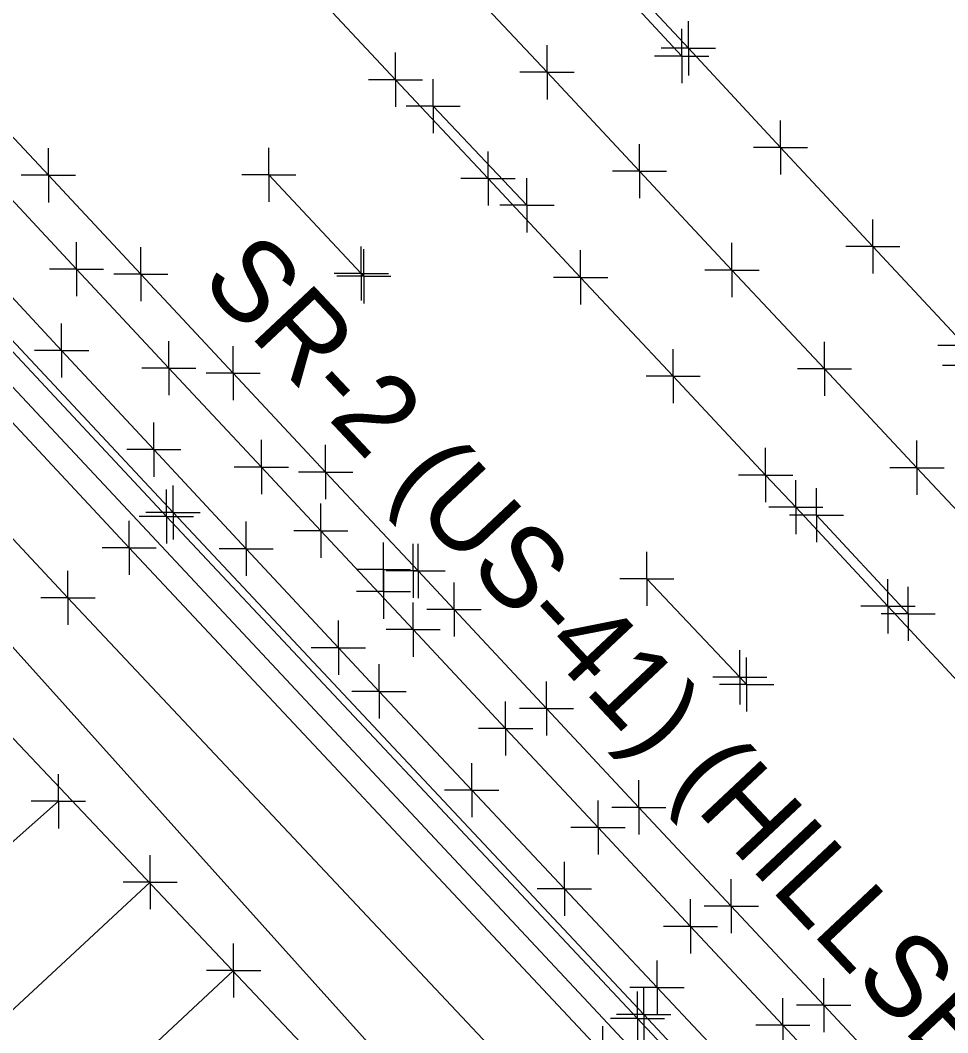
# Model space of a CAD drawing. Extents: x 0 to 1944463, y 0 to 420651.
# Drawn here: x 1943576.1 to 1943644.6, y 416958.1 to 417032.9 of the extents above; entities that cross this region are included whole.
import ezdxf

# ---------------------------------------------------------------- set-up
doc = ezdxf.new("R2010")
doc.units = 0
for name, color, linetype in [('SUR - DTM - Breaklines', 7, 'Continuous'), ('SUR - DTM - Breaklines - Points - Locators', 7, 'Continuous'), ('SUR - PROPERTY - Property Lines', 7, 'Continuous'), ('SUR - TR-CTRL - Pavement Marking', 7, 'Continuous'), ('SUR - TR-CTRL - Pavement Marking - Points - Locators', 7, 'Continuous'), ('SUR - TRAN - Features', 7, 'Continuous'), ('SUR - TRAN - Features - Points - Locators', 7, 'Continuous'), ('SUR - TRAN - Roads', 7, 'Continuous'), ('SUR - TRAN - Roads Text', 7, 'Continuous'), ('SUR - UTL - Fiber Optic Cable (Underground)', 7, 'Continuous'), ('SUR - UTL - Overhead Wire Crossings', 7, 'Continuous')]:
    doc.layers.add(name, color=color, linetype=linetype)

msp = doc.modelspace()

# ---------------------------------------------------------------- linework, layer by layer
at = {"layer": 'SUR - DTM - Breaklines'}
for points in [[(1943690.037, 416884.41), (1943687.662, 416887.901), (1943684.141, 416892.114), (1943657.009, 416921.299), (1943621.67, 416959.115), (1943586.87, 416996.211), (1943552.435, 417033.099), (1943548.063, 417037.789), (1943547.477, 417038.396), (1943544.67, 417041.299), (1943541.061, 417045.18), (1943540.584, 417045.813), (1943504.988, 417083.827), (1943481.846, 417108.505), (1943446.671, 417146.1), (1943414.771, 417178.279)], [(1943539.852, 417109.374), (1943546.682, 417102.07), (1943553.513, 417094.766), (1943560.343, 417087.462), (1943567.173, 417080.158), (1943574.003, 417072.854), (1943580.834, 417065.551), (1943587.664, 417058.247), (1943594.494, 417050.943), (1943601.325, 417043.639), (1943608.155, 417036.335), (1943614.985, 417029.031), (1943621.815, 417021.727), (1943628.646, 417014.423), (1943635.476, 417007.119), (1943642.306, 416999.815), (1943649.136, 416992.511), (1943655.967, 416985.207), (1943662.797, 416977.903), (1943669.627, 416970.599), (1943676.457, 416963.295), (1943683.288, 416955.991)]]:
    msp.add_lwpolyline(points, dxfattribs=at)
at = {"layer": 'SUR - DTM - Breaklines - Points - Locators'}
for p, q in [((1943614.985, 417029.031), (1943614.985, 417031.031)), ((1943614.985, 417029.031), (1943612.985, 417029.031)), ((1943614.985, 417029.031), (1943616.985, 417029.031)), ((1943614.985, 417029.031), (1943614.985, 417027.031)), ((1943621.815, 417021.727), (1943621.815, 417023.727)), ((1943621.815, 417021.727), (1943619.815, 417021.727)), ((1943621.815, 417021.727), (1943623.815, 417021.727)), ((1943621.815, 417021.727), (1943621.815, 417019.727)), ((1943628.646, 417014.423), (1943628.646, 417016.423)), ((1943628.646, 417014.423), (1943626.646, 417014.423)), ((1943628.646, 417014.423), (1943630.646, 417014.423)), ((1943628.646, 417014.423), (1943628.646, 417012.423)), ((1943635.476, 417007.119), (1943635.476, 417009.119)), ((1943635.476, 417007.119), (1943633.476, 417007.119)), ((1943635.476, 417007.119), (1943637.476, 417007.119)), ((1943635.476, 417007.119), (1943635.476, 417005.119)), ((1943642.306, 416999.815), (1943642.306, 417001.815)), ((1943642.306, 416999.815), (1943640.306, 416999.815)), ((1943642.306, 416999.815), (1943644.306, 416999.815)), ((1943642.306, 416999.815), (1943642.306, 416997.815)), ((1943586.87, 416996.211), (1943586.87, 416998.211)), ((1943586.87, 416996.211), (1943584.87, 416996.211)), ((1943586.87, 416996.211), (1943588.87, 416996.211)), ((1943586.87, 416996.211), (1943586.87, 416994.211)), ((1943621.67, 416959.115), (1943621.67, 416961.115)), ((1943621.67, 416959.115), (1943619.67, 416959.115)), ((1943621.67, 416959.115), (1943623.67, 416959.115)), ((1943621.67, 416959.115), (1943621.67, 416957.115))]:
    msp.add_line(p, q, dxfattribs=at)
at = {"layer": 'SUR - PROPERTY - Property Lines'}
for p, q in [((1943579.134, 417008.475), (1943579.134, 417010.475)), ((1943579.134, 417008.475), (1943577.134, 417008.475)), ((1943579.134, 417008.475), (1943581.134, 417008.475)), ((1943579.134, 417008.475), (1943579.134, 417006.475)), ((1943585.948, 417001.155), (1943585.948, 417003.155)), ((1943585.948, 417001.155), (1943583.948, 417001.155)), ((1943585.948, 417001.155), (1943587.948, 417001.155)), ((1943585.948, 417001.155), (1943585.948, 416999.155)), ((1943592.762, 416993.836), (1943592.762, 416995.836)), ((1943592.762, 416993.836), (1943590.762, 416993.836)), ((1943592.762, 416993.836), (1943594.762, 416993.836)), ((1943592.762, 416993.836), (1943592.762, 416991.836)), ((1943599.576, 416986.517), (1943599.576, 416988.517)), ((1943599.576, 416986.517), (1943597.576, 416986.517)), ((1943599.576, 416986.517), (1943601.576, 416986.517)), ((1943599.576, 416986.517), (1943599.576, 416984.517)), ((1943602.577, 416983.292), (1943602.577, 416985.292)), ((1943602.577, 416983.292), (1943600.577, 416983.292)), ((1943602.577, 416983.292), (1943604.577, 416983.292)), ((1943602.577, 416983.292), (1943602.577, 416981.292)), ((1943609.421, 416976.001), (1943609.421, 416978.001)), ((1943609.421, 416976.001), (1943607.421, 416976.001)), ((1943609.421, 416976.001), (1943611.421, 416976.001)), ((1943609.421, 416976.001), (1943609.421, 416974.001)), ((1943616.265, 416968.71), (1943616.265, 416970.71)), ((1943616.265, 416968.71), (1943614.265, 416968.71)), ((1943616.265, 416968.71), (1943618.265, 416968.71)), ((1943616.265, 416968.71), (1943616.265, 416966.71)), ((1943623.109, 416961.419), (1943623.109, 416963.419)), ((1943623.109, 416961.419), (1943621.109, 416961.419)), ((1943623.109, 416961.419), (1943625.109, 416961.419)), ((1943623.109, 416961.419), (1943623.109, 416959.419))]:
    msp.add_line(p, q, dxfattribs=at)
at = {"layer": 'SUR - TR-CTRL - Pavement Marking'}
for points in [[(1943550.497, 417111.213), (1943557.317, 417103.9), (1943564.137, 417096.586), (1943570.957, 417089.273), (1943577.778, 417081.96), (1943584.598, 417074.646), (1943591.418, 417067.333), (1943598.176, 417060.086), (1943604.988, 417052.765), (1943611.799, 417045.443), (1943618.611, 417038.122), (1943625.423, 417030.801), (1943632.234, 417023.479), (1943639.046, 417016.158), (1943645.857, 417008.837), (1943652.669, 417001.515), (1943655.246, 416998.746), (1943662.07, 416991.437), (1943668.895, 416984.128), (1943675.72, 416976.819), (1943682.545, 416969.51), (1943689.369, 416962.201), (1943696.194, 416954.892)], [(1943499.195, 417106.006), (1943506.035, 417098.711), (1943512.875, 417091.417), (1943519.716, 417084.122), (1943520.96, 417082.795), (1943527.773, 417075.474), (1943534.585, 417068.154), (1943541.397, 417060.833), (1943548.21, 417053.513), (1943555.022, 417046.192), (1943557.674, 417043.342), (1943564.5, 417036.034), (1943571.327, 417028.727), (1943578.153, 417021.419), (1943584.979, 417014.111), (1943591.805, 417006.803), (1943598.631, 416999.495), (1943605.457, 416992.187), (1943608.116, 416989.341), (1943614.942, 416982.033), (1943621.768, 416974.725), (1943628.595, 416967.418), (1943635.421, 416960.11), (1943642.247, 416952.802)], [(1943573.276, 417061.102), (1943576.462, 417057.683), (1943583.296, 417050.382), (1943590.13, 417043.082), (1943596.963, 417035.781), (1943603.797, 417028.481), (1943610.631, 417021.18), (1943617.465, 417013.879), (1943624.299, 417006.579), (1943631.133, 416999.278), (1943633.357, 416996.902), (1943640.169, 416989.581), (1943646.98, 416982.26), (1943653.792, 416974.938), (1943660.604, 416967.617), (1943667.416, 416960.296), (1943674.227, 416952.975)], [(1943618.188, 417037.513), (1943624.93, 417030.233)], [(1943606.569, 417026.524), (1943613.502, 417019.206)], [(1943594.432, 417021.46), (1943601.266, 417014.16), (1943601.456, 417013.957)], [(1943634.884, 416996.304), (1943641.665, 416989.024)], [(1943602.909, 416990.66), (1943602.909, 416992.302), (1943605.103, 416992.2)], [(1943622.363, 416991.612), (1943629.221, 416984.334), (1943629.729, 416983.795)], [(1943578.894, 416975.171), (1943564.666, 416962.579)], [(1943571.121, 416955.695), (1943585.673, 416969.203)], [(1943591.838, 416962.671), (1943577.197, 416949.004)]]:
    msp.add_lwpolyline(points, dxfattribs=at)
at = {"layer": 'SUR - TR-CTRL - Pavement Marking - Points - Locators'}
for p, q in [((1943625.423, 417030.801), (1943625.423, 417032.801)), ((1943624.93, 417030.233), (1943624.93, 417032.233)), ((1943625.423, 417030.801), (1943623.423, 417030.801)), ((1943625.423, 417030.801), (1943627.423, 417030.801)), ((1943625.423, 417030.801), (1943625.423, 417028.801)), ((1943603.797, 417028.481), (1943603.797, 417030.481)), ((1943624.93, 417030.233), (1943622.93, 417030.233)), ((1943624.93, 417030.233), (1943626.93, 417030.233)), ((1943624.93, 417030.233), (1943624.93, 417028.233)), ((1943603.797, 417028.481), (1943601.797, 417028.481)), ((1943603.797, 417028.481), (1943605.797, 417028.481)), ((1943603.797, 417028.481), (1943603.797, 417026.481)), ((1943606.569, 417026.524), (1943606.569, 417028.524)), ((1943606.569, 417026.524), (1943604.569, 417026.524)), ((1943606.569, 417026.524), (1943608.569, 417026.524)), ((1943606.569, 417026.524), (1943606.569, 417024.524)), ((1943632.234, 417023.479), (1943632.234, 417025.479)), ((1943578.153, 417021.419), (1943578.153, 417023.419)), ((1943594.432, 417021.46), (1943594.432, 417023.46)), ((1943632.234, 417023.479), (1943630.234, 417023.479)), ((1943632.234, 417023.479), (1943634.234, 417023.479)), ((1943632.234, 417023.479), (1943632.234, 417021.479)), ((1943610.631, 417021.18), (1943610.631, 417023.18)), ((1943578.153, 417021.419), (1943576.153, 417021.419)), ((1943578.153, 417021.419), (1943580.153, 417021.419)), ((1943578.153, 417021.419), (1943578.153, 417019.419)), ((1943594.432, 417021.46), (1943592.432, 417021.46)), ((1943594.432, 417021.46), (1943596.432, 417021.46)), ((1943594.432, 417021.46), (1943594.432, 417019.46)), ((1943610.631, 417021.18), (1943608.631, 417021.18)), ((1943610.631, 417021.18), (1943612.631, 417021.18)), ((1943610.631, 417021.18), (1943610.631, 417019.18)), ((1943613.502, 417019.206), (1943613.502, 417021.206)), ((1943613.502, 417019.206), (1943611.502, 417019.206)), ((1943613.502, 417019.206), (1943615.502, 417019.206)), ((1943613.502, 417019.206), (1943613.502, 417017.206)), ((1943639.046, 417016.158), (1943639.046, 417018.158)), ((1943584.979, 417014.111), (1943584.979, 417016.111)), ((1943601.266, 417014.16), (1943601.266, 417016.16)), ((1943601.456, 417013.957), (1943601.456, 417015.957)), ((1943617.465, 417013.879), (1943617.465, 417015.879)), ((1943639.046, 417016.158), (1943637.046, 417016.158)), ((1943639.046, 417016.158), (1943641.046, 417016.158)), ((1943639.046, 417016.158), (1943639.046, 417014.158)), ((1943584.979, 417014.111), (1943582.979, 417014.111)), ((1943584.979, 417014.111), (1943586.979, 417014.111)), ((1943584.979, 417014.111), (1943584.979, 417012.111)), ((1943601.266, 417014.16), (1943599.266, 417014.16)), ((1943601.456, 417013.957), (1943599.456, 417013.957)), ((1943601.266, 417014.16), (1943603.266, 417014.16)), ((1943601.266, 417014.16), (1943601.266, 417012.16)), ((1943601.456, 417013.957), (1943603.456, 417013.957)), ((1943601.456, 417013.957), (1943601.456, 417011.957)), ((1943617.465, 417013.879), (1943615.465, 417013.879)), ((1943617.465, 417013.879), (1943619.465, 417013.879)), ((1943617.465, 417013.879), (1943617.465, 417011.879)), ((1943591.805, 417006.803), (1943591.805, 417008.803)), ((1943624.299, 417006.579), (1943624.299, 417008.579)), ((1943645.857, 417008.837), (1943643.857, 417008.837)), ((1943646.187, 417007.368), (1943644.187, 417007.368)), ((1943591.805, 417006.803), (1943589.805, 417006.803)), ((1943591.805, 417006.803), (1943593.805, 417006.803)), ((1943591.805, 417006.803), (1943591.805, 417004.803)), ((1943624.299, 417006.579), (1943622.299, 417006.579)), ((1943624.299, 417006.579), (1943626.299, 417006.579)), ((1943624.299, 417006.579), (1943624.299, 417004.579)), ((1943598.631, 416999.495), (1943598.631, 417001.495)), ((1943631.133, 416999.278), (1943631.133, 417001.278)), ((1943598.631, 416999.495), (1943596.631, 416999.495)), ((1943598.631, 416999.495), (1943600.631, 416999.495)), ((1943598.631, 416999.495), (1943598.631, 416997.495)), ((1943631.133, 416999.278), (1943629.133, 416999.278)), ((1943631.133, 416999.278), (1943633.133, 416999.278)), ((1943631.133, 416999.278), (1943631.133, 416997.278)), ((1943633.357, 416996.902), (1943633.357, 416998.902)), ((1943634.884, 416996.304), (1943634.884, 416998.304)), ((1943633.357, 416996.902), (1943631.357, 416996.902)), ((1943633.357, 416996.902), (1943635.357, 416996.902)), ((1943633.357, 416996.902), (1943633.357, 416994.902)), ((1943634.884, 416996.304), (1943632.884, 416996.304)), ((1943634.884, 416996.304), (1943636.884, 416996.304)), ((1943634.884, 416996.304), (1943634.884, 416994.304)), ((1943602.909, 416992.302), (1943602.909, 416994.302)), ((1943605.103, 416992.2), (1943605.103, 416994.2)), ((1943605.457, 416992.187), (1943605.457, 416994.187)), ((1943622.363, 416991.612), (1943622.363, 416993.612)), ((1943602.909, 416990.66), (1943602.909, 416992.66)), ((1943602.909, 416992.302), (1943600.909, 416992.302)), ((1943602.909, 416992.302), (1943604.909, 416992.302)), ((1943602.909, 416992.302), (1943602.909, 416990.302)), ((1943605.103, 416992.2), (1943603.103, 416992.2)), ((1943605.457, 416992.187), (1943603.457, 416992.187)), ((1943605.103, 416992.2), (1943607.103, 416992.2)), ((1943605.103, 416992.2), (1943605.103, 416990.2)), ((1943605.457, 416992.187), (1943607.457, 416992.187)), ((1943605.457, 416992.187), (1943605.457, 416990.187)), ((1943608.116, 416989.341), (1943608.116, 416991.341)), ((1943622.363, 416991.612), (1943620.363, 416991.612)), ((1943622.363, 416991.612), (1943624.363, 416991.612)), ((1943622.363, 416991.612), (1943622.363, 416989.612)), ((1943640.169, 416989.581), (1943640.169, 416991.581)), ((1943602.909, 416990.66), (1943600.909, 416990.66)), ((1943602.909, 416990.66), (1943604.909, 416990.66)), ((1943602.909, 416990.66), (1943602.909, 416988.66)), ((1943641.665, 416989.024), (1943641.665, 416991.024)), ((1943608.116, 416989.341), (1943606.116, 416989.341)), ((1943608.116, 416989.341), (1943610.116, 416989.341)), ((1943608.116, 416989.341), (1943608.116, 416987.341)), ((1943640.169, 416989.581), (1943638.169, 416989.581)), ((1943641.665, 416989.024), (1943639.665, 416989.024)), ((1943640.169, 416989.581), (1943642.169, 416989.581)), ((1943640.169, 416989.581), (1943640.169, 416987.581)), ((1943641.665, 416989.024), (1943643.665, 416989.024)), ((1943641.665, 416989.024), (1943641.665, 416987.024)), ((1943629.221, 416984.334), (1943629.221, 416986.334)), ((1943629.729, 416983.795), (1943629.729, 416985.795)), ((1943614.942, 416982.033), (1943614.942, 416984.033)), ((1943629.221, 416984.334), (1943627.221, 416984.334)), ((1943629.729, 416983.795), (1943627.729, 416983.795)), ((1943629.221, 416984.334), (1943631.221, 416984.334)), ((1943629.221, 416984.334), (1943629.221, 416982.334)), ((1943629.729, 416983.795), (1943631.729, 416983.795)), ((1943629.729, 416983.795), (1943629.729, 416981.795)), ((1943614.942, 416982.033), (1943612.942, 416982.033)), ((1943614.942, 416982.033), (1943616.942, 416982.033)), ((1943614.942, 416982.033), (1943614.942, 416980.033)), ((1943578.894, 416975.171), (1943578.894, 416977.171)), ((1943621.768, 416974.725), (1943621.768, 416976.725)), ((1943578.894, 416975.171), (1943576.894, 416975.171)), ((1943578.894, 416975.171), (1943580.894, 416975.171)), ((1943578.894, 416975.171), (1943578.894, 416973.171)), ((1943621.768, 416974.725), (1943619.768, 416974.725)), ((1943621.768, 416974.725), (1943623.768, 416974.725)), ((1943621.768, 416974.725), (1943621.768, 416972.725)), ((1943585.673, 416969.203), (1943585.673, 416971.203)), ((1943585.673, 416969.203), (1943583.673, 416969.203)), ((1943585.673, 416969.203), (1943587.673, 416969.203)), ((1943585.673, 416969.203), (1943585.673, 416967.203)), ((1943628.595, 416967.418), (1943628.595, 416969.418)), ((1943628.595, 416967.418), (1943626.595, 416967.418)), ((1943628.595, 416967.418), (1943630.595, 416967.418)), ((1943628.595, 416967.418), (1943628.595, 416965.418)), ((1943591.838, 416962.671), (1943591.838, 416964.671)), ((1943591.838, 416962.671), (1943589.838, 416962.671)), ((1943591.838, 416962.671), (1943593.838, 416962.671)), ((1943591.838, 416962.671), (1943591.838, 416960.671)), ((1943635.421, 416960.11), (1943635.421, 416962.11)), ((1943635.421, 416960.11), (1943633.421, 416960.11)), ((1943635.421, 416960.11), (1943637.421, 416960.11)), ((1943635.421, 416960.11), (1943635.421, 416958.11))]:
    msp.add_line(p, q, dxfattribs=at)
at = {"layer": 'SUR - TRAN - Features'}
for points in [[(1943690.517, 416884.687), (1943688.171, 416888.179), (1943684.491, 416892.496), (1943657.382, 416921.566), (1943622.127, 416959.409), (1943587.363, 416996.51), (1943552.883, 417033.403), (1943548.422, 417038.143), (1943540.877, 417046.253), (1943505.414, 417084.161), (1943482.193, 417108.964), (1943447.041, 417146.494), (1943415.051, 417178.837)], [(1943683.475, 416879.002), (1943650.193, 416914.722), (1943614.895, 416952.654), (1943579.604, 416990.202), (1943545.778, 417026.452), (1943534.226, 417038.899), (1943498.133, 417077.367), (1943475.267, 417101.767), (1943439.87, 417139.584), (1943410.719, 417170.507), (1943406.186, 417175.311), (1943401.196, 417176.55), (1943395.893, 417176.476), (1943388.428, 417174.941), (1943381.482, 417171.318), (1943374.135, 417163.898), (1943371.169, 417159.245), (1943367.675, 417150.231), (1943360.721, 417127.894)], [(1943697.4, 416860.877), (1943690.662, 416853.516), (1943680.011, 416848.771), (1943671.071, 416850.108), (1943659.172, 416861.163), (1943671.245, 416876.496), (1943646.14, 416904.56), (1943621.368, 416931.316), (1943572.636, 416982.883), (1943540.39, 417017.544), (1943505.699, 417054.06), (1943474.434, 417087.298), (1943457.685, 417072.554), (1943450.018, 417075.306), (1943447.742, 417078.93), (1943449.061, 417085.558), (1943418.603, 417095.278), (1943390.386, 417103.24), (1943385.223, 417087.294), (1943382.77, 417085.376), (1943380.03, 417085.521), (1943353.12, 417094.43), (1943345.493, 417101.695)], [(1943497.263, 417103.321), (1943504.089, 417096.012), (1943510.914, 417088.704), (1943517.74, 417081.396), (1943523.951, 417074.745), (1943530.777, 417067.436), (1943537.602, 417060.128), (1943544.428, 417052.82), (1943551.253, 417045.511), (1943552.931, 417043.715), (1943559.756, 417036.407), (1943566.582, 417029.098), (1943573.407, 417021.79), (1943580.233, 417014.481), (1943587.058, 417007.173), (1943593.884, 416999.865), (1943598.274, 416995.164), (1943605.099, 416987.855), (1943611.925, 416980.547), (1943618.75, 416973.238), (1943625.576, 416965.93), (1943632.401, 416958.621), (1943639.227, 416951.313)], [(1943689.969, 416884.205), (1943688.032, 416882.685), (1943654.543, 416918.706), (1943619.098, 416956.562), (1943584.119, 416993.893), (1943550.009, 417030.506), (1943545.291, 417035.524), (1943547.776, 417037.81)]]:
    msp.add_lwpolyline(points, dxfattribs=at)
at = {"layer": 'SUR - TRAN - Features - Points - Locators'}
for p, q in [((1943580.233, 417014.481), (1943580.233, 417016.481)), ((1943580.233, 417014.481), (1943578.233, 417014.481)), ((1943580.233, 417014.481), (1943582.233, 417014.481)), ((1943580.233, 417014.481), (1943580.233, 417012.481)), ((1943587.058, 417007.173), (1943587.058, 417009.173)), ((1943587.058, 417007.173), (1943585.058, 417007.173)), ((1943587.058, 417007.173), (1943589.058, 417007.173)), ((1943587.058, 417007.173), (1943587.058, 417005.173)), ((1943593.884, 416999.865), (1943593.884, 417001.865)), ((1943593.884, 416999.865), (1943591.884, 416999.865)), ((1943593.884, 416999.865), (1943595.884, 416999.865)), ((1943593.884, 416999.865), (1943593.884, 416997.865)), ((1943587.363, 416996.51), (1943587.363, 416998.51)), ((1943598.274, 416995.164), (1943598.274, 416997.164)), ((1943587.363, 416996.51), (1943585.363, 416996.51)), ((1943587.363, 416996.51), (1943589.363, 416996.51)), ((1943587.363, 416996.51), (1943587.363, 416994.51)), ((1943584.119, 416993.893), (1943584.119, 416995.893)), ((1943598.274, 416995.164), (1943596.274, 416995.164)), ((1943598.274, 416995.164), (1943600.274, 416995.164)), ((1943598.274, 416995.164), (1943598.274, 416993.164)), ((1943584.119, 416993.893), (1943582.119, 416993.893)), ((1943584.119, 416993.893), (1943586.119, 416993.893)), ((1943584.119, 416993.893), (1943584.119, 416991.893)), ((1943579.604, 416990.202), (1943579.604, 416992.202)), ((1943579.604, 416990.202), (1943577.604, 416990.202)), ((1943579.604, 416990.202), (1943581.604, 416990.202)), ((1943579.604, 416990.202), (1943579.604, 416988.202)), ((1943605.099, 416987.855), (1943605.099, 416989.855)), ((1943605.099, 416987.855), (1943603.099, 416987.855)), ((1943605.099, 416987.855), (1943607.099, 416987.855)), ((1943605.099, 416987.855), (1943605.099, 416985.855)), ((1943611.925, 416980.547), (1943611.925, 416982.547)), ((1943611.925, 416980.547), (1943609.925, 416980.547)), ((1943611.925, 416980.547), (1943613.925, 416980.547)), ((1943611.925, 416980.547), (1943611.925, 416978.547)), ((1943618.75, 416973.238), (1943618.75, 416975.238)), ((1943618.75, 416973.238), (1943616.75, 416973.238)), ((1943618.75, 416973.238), (1943620.75, 416973.238)), ((1943618.75, 416973.238), (1943618.75, 416971.238)), ((1943625.576, 416965.93), (1943625.576, 416967.93)), ((1943625.576, 416965.93), (1943623.576, 416965.93)), ((1943625.576, 416965.93), (1943627.576, 416965.93)), ((1943625.576, 416965.93), (1943625.576, 416963.93)), ((1943622.127, 416959.409), (1943622.127, 416961.409)), ((1943632.401, 416958.621), (1943632.401, 416960.621)), ((1943622.127, 416959.409), (1943620.127, 416959.409)), ((1943622.127, 416959.409), (1943624.127, 416959.409)), ((1943622.127, 416959.409), (1943622.127, 416957.409)), ((1943619.098, 416956.562), (1943619.098, 416958.562)), ((1943632.401, 416958.621), (1943630.401, 416958.621)), ((1943632.401, 416958.621), (1943634.401, 416958.621)), ((1943632.401, 416958.621), (1943632.401, 416956.621))]:
    msp.add_line(p, q, dxfattribs=at)
at = {"layer": 'SUR - TRAN - Roads'}
msp.add_lwpolyline([(1943500.316, 417093.058), (1943507.153, 417085.76), (1943512.354, 417080.209), (1943519.168, 417072.889), (1943525.982, 417065.57), (1943532.796, 417058.251), (1943539.609, 417050.932), (1943546.423, 417043.612), (1943551.879, 417037.752), (1943558.693, 417030.433), (1943565.507, 417023.113), (1943572.32, 417015.794), (1943579.134, 417008.475), (1943585.948, 417001.155), (1943592.762, 416993.836), (1943599.576, 416986.517), (1943602.577, 416983.292), (1943609.421, 416976.001), (1943616.265, 416968.71), (1943623.109, 416961.419), (1943629.953, 416954.127)], dxfattribs=at)
at = {"layer": 'SUR - UTL - Fiber Optic Cable (Underground)'}
msp.add_lwpolyline([(1943675.935, 416874.811), (1943301.532, 417291.453), (1943229.017, 417377.593), (1943204.769, 417412.08), (1943079.474, 417545.559), (1943001.447, 417611.824), (1942943.851, 417666.04), (1942875.969, 417717.873), (1942785.445, 417773.544), (1942671.047, 417813.855), (1942647.996, 417834.422), (1942364.461, 417940.541)], dxfattribs=at)
at = {"layer": 'SUR - UTL - Overhead Wire Crossings'}
msp.add_lwpolyline([(1943644.273, 416932.242), (1943530.467, 417053.971)], dxfattribs=at)

# ---------------------------------------------------------------- texts
at = {"layer": 'SUR - TRAN - Roads Text'}
msp.add_text('SR-2 (US-41) (HILLSBORO BLVD.) (ASP.)', height=5.99999, rotation=313.22626, dxfattribs=at).set_placement((1943589.28, 417013.519))

doc.saveas('drawing.dxf')
